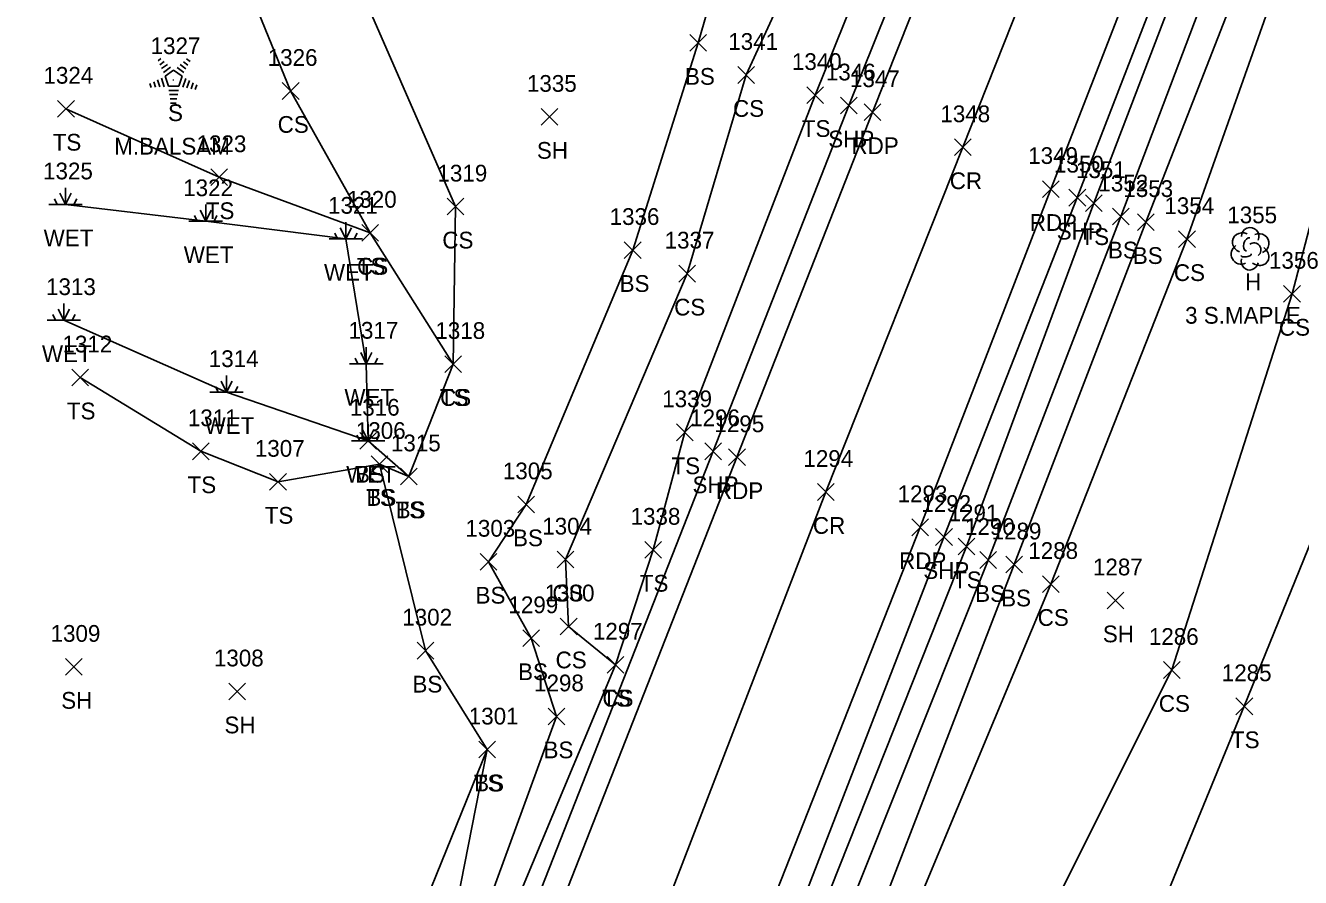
# Model space of a CAD drawing. Extents: x 1554917 to 1555870, y 813367 to 816333.
# Drawn here: x 1555040.5 to 1555192.9, y 813759.7 to 813861.5 of the extents above; entities that cross this region are included whole.
import ezdxf

# ---------------------------------------------------------------- set-up
doc = ezdxf.new("R2010")
doc.units = 0
for name, color, linetype in [('L_A', 7, 'Continuous'), ('L_C', 7, 'Continuous'), ('L_I', 7, 'Continuous'), ('L_TIC', 7, 'Continuous'), ('LELB', 7, 'Continuous'), ('LTC', 7, 'Continuous'), ('LTD', 7, 'Continuous'), ('LWET', 7, 'Continuous'), ('P_A', 7, 'Continuous'), ('P_I', 7, 'Continuous'), ('P_TIC', 7, 'Continuous'), ('PET', 7, 'Continuous'), ('PRC', 7, 'Continuous'), ('PSP', 7, 'Continuous')]:
    doc.layers.add(name, color=color, linetype=linetype)

msp = doc.modelspace()

# ---------------------------------------------------------------- linework, layer by layer
at = {"layer": 'L_TIC'}
for points in [[(1555119.88, 813858.4), (1555121.88, 813860.4)], [(1555121.88, 813858.4), (1555119.88, 813860.4)], [(1555125.62, 813854.57), (1555127.62, 813856.57)], [(1555127.62, 813854.57), (1555125.62, 813856.57)], [(1555071.21, 813852.66), (1555073.21, 813854.66)], [(1555073.21, 813852.66), (1555071.21, 813854.66)], [(1555133.87, 813852.17), (1555135.87, 813854.17)], [(1555135.87, 813852.17), (1555133.87, 813854.17)], [(1555044.37, 813850.53), (1555046.37, 813852.53)], [(1555046.37, 813850.53), (1555044.37, 813852.53)], [(1555102.14, 813849.56), (1555104.14, 813851.56)], [(1555104.14, 813849.56), (1555102.14, 813851.56)], [(1555062.66, 813842.35), (1555064.66, 813844.35)], [(1555064.66, 813842.35), (1555062.66, 813844.35)], [(1555090.89, 813838.84), (1555092.89, 813840.84)], [(1555092.89, 813838.84), (1555090.89, 813840.84)], [(1555167.16, 813839.25), (1555169.16, 813841.25)], [(1555169.16, 813839.25), (1555167.16, 813841.25)], [(1555170.4, 813837.65), (1555172.4, 813839.65)], [(1555172.4, 813837.65), (1555170.4, 813839.65)], [(1555080.71, 813835.71), (1555082.71, 813837.71)], [(1555082.71, 813835.71), (1555080.71, 813837.71)], [(1555080.71, 813835.71), (1555082.71, 813837.71)], [(1555082.71, 813835.71), (1555080.71, 813837.71)], [(1555173.38, 813836.99), (1555175.38, 813838.99)], [(1555175.38, 813836.99), (1555173.38, 813838.99)], [(1555178.29, 813834.95), (1555180.29, 813836.95)], [(1555180.29, 813834.95), (1555178.29, 813836.95)], [(1555112.07, 813833.65), (1555114.07, 813835.65)], [(1555114.07, 813833.65), (1555112.07, 813835.65)], [(1555118.58, 813830.83), (1555120.58, 813832.83)], [(1555120.58, 813830.83), (1555118.58, 813832.83)], [(1555190.84, 813828.42), (1555192.84, 813830.42)], [(1555192.84, 813828.42), (1555190.84, 813830.42)], [(1555090.62, 813820.03), (1555092.62, 813822.03)], [(1555092.62, 813820.03), (1555090.62, 813822.03)], [(1555090.62, 813820.03), (1555092.62, 813822.03)], [(1555092.62, 813820.03), (1555090.62, 813822.03)], [(1555046.07, 813818.42), (1555048.07, 813820.42)], [(1555048.07, 813818.42), (1555046.07, 813820.42)], [(1555118.3, 813811.87), (1555120.3, 813813.87)], [(1555120.3, 813811.87), (1555118.3, 813813.87)], [(1555080.46, 813810.86), (1555082.46, 813812.86)], [(1555082.46, 813810.86), (1555080.46, 813812.86)], [(1555060.49, 813809.6), (1555062.49, 813811.6)], [(1555062.49, 813809.6), (1555060.49, 813811.6)], [(1555081.82, 813808.08), (1555083.82, 813810.08)], [(1555083.82, 813808.08), (1555081.82, 813810.08)], [(1555081.82, 813808.08), (1555083.82, 813810.08)], [(1555083.82, 813808.08), (1555081.82, 813810.08)], [(1555085.32, 813806.6), (1555087.32, 813808.6)], [(1555087.32, 813806.6), (1555085.32, 813808.6)], [(1555085.32, 813806.6), (1555087.32, 813808.6)], [(1555087.32, 813806.6), (1555085.32, 813808.6)], [(1555069.7, 813805.95), (1555071.7, 813807.95)], [(1555071.7, 813805.95), (1555069.7, 813807.95)], [(1555099.34, 813803.26), (1555101.34, 813805.26)], [(1555101.34, 813803.26), (1555099.34, 813805.26)], [(1555114.51, 813797.83), (1555116.51, 813799.83)], [(1555116.51, 813797.83), (1555114.51, 813799.83)], [(1555151.94, 813798.24), (1555153.94, 813800.24)], [(1555153.94, 813798.24), (1555151.94, 813800.24)], [(1555094.86, 813796.4), (1555096.86, 813798.4)], [(1555096.86, 813796.4), (1555094.86, 813798.4)], [(1555104.04, 813796.66), (1555106.04, 813798.66)], [(1555106.04, 813796.66), (1555104.04, 813798.66)], [(1555154.55, 813796.61), (1555156.55, 813798.61)], [(1555156.55, 813796.61), (1555154.55, 813798.61)], [(1555157.65, 813796.07), (1555159.65, 813798.07)], [(1555159.65, 813796.07), (1555157.65, 813798.07)], [(1555162.02, 813793.74), (1555164.02, 813795.74)], [(1555164.02, 813793.74), (1555162.02, 813795.74)], [(1555169.75, 813791.78), (1555171.75, 813793.78)], [(1555171.75, 813791.78), (1555169.75, 813793.78)], [(1555104.42, 813788.67), (1555106.42, 813790.67)], [(1555106.42, 813788.67), (1555104.42, 813790.67)], [(1555099.94, 813787.26), (1555101.94, 813789.26)], [(1555101.94, 813787.26), (1555099.94, 813789.26)], [(1555087.32, 813785.78), (1555089.32, 813787.78)], [(1555089.32, 813785.78), (1555087.32, 813787.78)], [(1555045.31, 813783.84), (1555047.31, 813785.84)], [(1555047.31, 813783.84), (1555045.31, 813785.84)], [(1555110.01, 813784.1), (1555112.01, 813786.1)], [(1555112.01, 813784.1), (1555110.01, 813786.1)], [(1555110.01, 813784.1), (1555112.01, 813786.1)], [(1555112.01, 813784.1), (1555110.01, 813786.1)], [(1555176.49, 813783.47), (1555178.49, 813785.47)], [(1555178.49, 813783.47), (1555176.49, 813785.47)], [(1555064.82, 813780.9), (1555066.82, 813782.9)], [(1555066.82, 813780.9), (1555064.82, 813782.9)], [(1555102.98, 813777.92), (1555104.98, 813779.92)], [(1555104.98, 813777.92), (1555102.98, 813779.92)], [(1555185.14, 813779.13), (1555187.14, 813781.13)], [(1555187.14, 813779.13), (1555185.14, 813781.13)], [(1555094.69, 813773.96), (1555096.69, 813775.96)], [(1555096.69, 813773.96), (1555094.69, 813775.96)], [(1555094.69, 813773.96), (1555096.69, 813775.96)], [(1555096.69, 813773.96), (1555094.69, 813775.96)]]:
    msp.add_lwpolyline(points, dxfattribs=at)
at = {"layer": 'LELB'}
for points in [[(1555019.54, 813585.69), (1555024.77, 813597.99), (1555042.65, 813620.9), (1555048.58, 813631.85), (1555066.52, 813674.6), (1555093.66, 813750.68), (1555103.98, 813778.92), (1555100.94, 813788.26), (1555095.86, 813797.4), (1555100.34, 813804.26), (1555113.07, 813834.65), (1555120.88, 813859.4), (1555126.12, 813877.4), (1555144.96, 813909.35), (1555149.61, 813919.5), (1555153.95, 813930.09), (1555158.29, 813940)], [(1554960.86, 813387.22), (1554975.88, 813430.61), (1554997.67, 813492.71), (1555013.89, 813538.05), (1555028.68, 813579.18), (1555048.82, 813626.54), (1555068.18, 813674.18), (1555096.05, 813749.22), (1555111.01, 813785.1), (1555115.51, 813798.83), (1555119.3, 813812.87), (1555134.87, 813853.17), (1555141.95, 813870.8), (1555155.34, 813907.69), (1555153.32, 813917.67), (1555161.57, 813925.65), (1555168.92, 813938.89)], [(1555101.22, 813603.84), (1555111.95, 813631.93), (1555127.97, 813651.43), (1555152.02, 813699.54), (1555162.91, 813721.01), (1555173.86, 813750.23), (1555186.14, 813780.13), (1555202.44, 813820.35), (1555215.18, 813875.95), (1555215.28, 813897.96), (1555212.9, 813910.7), (1555212.19, 813917.21), (1555210.66, 813920.37), (1555207.16, 813922.92), (1555203.03, 813922.76), (1555199.5, 813919.6)], [(1555091.02, 813589.64), (1555093.93, 813609.08), (1555110.01, 813657.36), (1555123.68, 813699.33), (1555136.3, 813730.66), (1555163.02, 813794.74), (1555179.29, 813835.95), (1555197.25, 813886.69), (1555209.44, 813915.13), (1555210.66, 813920.37)], [(1554992.4, 813377.01), (1555009.62, 813423.34), (1555030.72, 813482.86), (1555047.7, 813528.1), (1555056, 813550.42), (1555062.05, 813566.99), (1555080.33, 813615.57), (1555099.41, 813662.25), (1555114.13, 813700.62), (1555127, 813733.84), (1555152.94, 813799.24), (1555168.16, 813840.25), (1555187.47, 813890.8), (1555199.5, 813919.6)], [(1555111.01, 813785.1), (1555105.42, 813789.67), (1555105.04, 813797.66), (1555119.58, 813831.83), (1555126.62, 813855.57), (1555135.55, 813874.97), (1555151.3, 813907.75), (1555149.61, 813919.5)], [(1554997.34, 813375.96), (1555001.03, 813380.2), (1555008.26, 813399.3), (1555016.85, 813422.36), (1555039.01, 813478.41), (1555055.21, 813525.71), (1555062.73, 813548.53), (1555066.84, 813564.4), (1555085.89, 813613.91), (1555101.8, 813661.36), (1555117.2, 813700.9), (1555129.69, 813732.82), (1555155.55, 813797.61), (1555171.4, 813838.65), (1555190.74, 813889.78), (1555201.42, 813914.42), (1555204.39, 813917.83), (1555206.44, 813916.94)], [(1555060.32, 813524.58), (1555067.83, 813537.87), (1555070.43, 813550.96), (1555072.05, 813560.86), (1555087.88, 813613.15), (1555106.35, 813658.95), (1555120.2, 813700.04), (1555133.19, 813731.1), (1555158.65, 813797.07), (1555174.38, 813837.99), (1555194.21, 813888.82), (1555206.44, 813916.94)], [(1555111.95, 813631.93), (1555123.2, 813652.42), (1555137.56, 813696.49), (1555156.74, 813743.02), (1555177.49, 813784.47), (1555191.84, 813829.42), (1555205.71, 813882.43), (1555212.9, 813910.7)], [(1555091.62, 813821.03), (1555091.89, 813839.84), (1555078.83, 813869.78), (1555066.4, 813889.61)], [(1555081.71, 813836.71), (1555072.21, 813853.66), (1555063.46, 813875.06)], [(1555086.32, 813807.6), (1555091.62, 813821.03), (1555081.71, 813836.71), (1555063.66, 813843.35), (1555045.37, 813851.53)], [(1555082.82, 813809.08), (1555070.7, 813806.95), (1555061.49, 813810.6), (1555047.07, 813819.42)], [(1554949.33, 813611.76), (1554977.21, 813618.67), (1554998.22, 813624.91), (1555016.24, 813625.01), (1555029.3, 813621.81), (1555040.32, 813624.75), (1555045.98, 813633.07), (1555049.32, 813640.6), (1555063.34, 813676.25), (1555081.89, 813724.28), (1555091.18, 813752.08), (1555095.69, 813774.96), (1555088.32, 813786.78), (1555082.82, 813809.08), (1555086.32, 813807.6), (1555081.46, 813811.86)], [(1554954.51, 813629.31), (1554971.74, 813631.07), (1554998.18, 813639.71), (1555016.83, 813638), (1555031.95, 813634.95), (1555041.94, 813634.59), (1555045.91, 813643.15), (1555048.09, 813658.42), (1555054.81, 813682.71), (1555073.55, 813727.86), (1555077.68, 813738.56), (1555087.17, 813753.94), (1555095.69, 813774.96)]]:
    msp.add_lwpolyline(points, dxfattribs=at)
at = {"layer": 'LTC'}
for p, q in [((1555056.37, 813857.26), (1555056.72, 813857.52)), ((1555059.77, 813857.5), (1555060.19, 813857.2)), ((1555056.58, 813856.8), (1555057.11, 813857.18)), ((1555056.79, 813856.33), (1555057.49, 813856.84)), ((1555057, 813855.87), (1555057.87, 813856.5)), ((1555057.22, 813855.41), (1555058.23, 813856.15)), ((1555058.23, 813856.15), (1555059.23, 813855.42)), ((1555058.65, 813856.46), (1555059.46, 813855.87)), ((1555059.02, 813856.81), (1555059.7, 813856.31)), ((1555059.39, 813857.16), (1555059.94, 813856.76)), ((1555055.4, 813854.54), (1555055.55, 813854.08)), ((1555055.86, 813854.76), (1555056.07, 813854.11)), ((1555056.31, 813854.98), (1555056.58, 813854.14)), ((1555056.77, 813855.19), (1555057.1, 813854.17)), ((1555057.22, 813855.41), (1555057.61, 813854.22)), ((1555059.23, 813855.42), (1555058.84, 813854.22)), ((1555059.67, 813855.15), (1555059.33, 813854.11)), ((1555060.11, 813854.9), (1555059.82, 813854.02)), ((1555060.56, 813854.65), (1555060.32, 813853.92)), ((1555061, 813854.4), (1555060.81, 813853.83)), ((1555058.84, 813854.22), (1555057.61, 813854.22)), ((1555058.8, 813853.72), (1555057.66, 813853.72)), ((1555058.72, 813853.22), (1555057.73, 813853.22)), ((1555058.63, 813852.72), (1555057.8, 813852.72)), ((1555058.55, 813852.22), (1555057.87, 813852.22))]:
    msp.add_line(p, q, dxfattribs=at)
at = {"layer": 'LTD'}
msp.add_line((1555186.8, 813834.85), (1555186.8, 813834.85), dxfattribs=at)
msp.add_line((1555186.8, 813834.85), (1555186.8, 813834.85), dxfattribs=at)
msp.add_arc((1555186.85, 813836.28), 1.05, 335.5272, 180.9563, dxfattribs=at)
for centre, major_axis, ratio, start_param, end_param in [((1555186.01, 813835.52), (1.21, -0.51), 0.895232, 1.570796, 4.712389), ((1555186.6, 813835.31), (-0.208, -0.792), 0.645439, 3.141593, 6.283185), ((1555187.85, 813835.43), (-1.14, -0.48), 0.949671, 1.570796, 4.712389), ((1555185.72, 813834.14), (0.58, -1.04), 0.959034, 3.141593, 6.283185), ((1555187.3, 813834.68), (-0.5, 0.667), 0.989748, 3.141593, 6.283185), ((1555187.8, 813834.02), (-1.09, 0.79), 0.841452, 1.570796, 4.712389), ((1555186.8, 813833.35), (0.26, 1.06), 0.942809, 1.570796, 4.712389), ((1555186.35, 813834.1), (-0.625, -0.083), 0.423636, 0, 3.141593)]:
    msp.add_ellipse(centre, major_axis=major_axis, ratio=ratio, start_param=start_param, end_param=end_param, dxfattribs=at)
at = {"layer": 'LWET'}
for p, q in [((1555045.32, 813840.1), (1555045.32, 813842.1)), ((1555044.32, 813840.1), (1555043.99, 813840.76)), ((1555045.32, 813840.1), (1555044.65, 813841.43)), ((1555045.32, 813840.1), (1555045.99, 813841.43)), ((1555046.32, 813840.1), (1555046.65, 813840.76)), ((1555047.32, 813840.1), (1555043.32, 813840.1)), ((1555062.06, 813838.09), (1555061.39, 813839.43)), ((1555062.06, 813838.09), (1555062.06, 813840.09)), ((1555062.06, 813838.09), (1555062.73, 813839.43)), ((1555064.06, 813838.09), (1555060.06, 813838.09)), ((1555061.06, 813838.09), (1555060.73, 813838.76)), ((1555063.06, 813838.09), (1555063.39, 813838.76)), ((1555078.81, 813835.99), (1555078.81, 813837.99)), ((1555080.81, 813835.99), (1555076.81, 813835.99)), ((1555077.81, 813835.99), (1555077.48, 813836.65)), ((1555078.81, 813835.99), (1555078.14, 813837.32)), ((1555078.81, 813835.99), (1555079.48, 813837.32)), ((1555079.81, 813835.99), (1555080.14, 813836.65)), ((1555044.12, 813826.27), (1555043.78, 813826.93)), ((1555045.12, 813826.27), (1555044.45, 813827.6)), ((1555045.12, 813826.27), (1555045.12, 813828.27)), ((1555045.12, 813826.27), (1555045.78, 813827.6)), ((1555046.12, 813826.27), (1555046.45, 813826.93)), ((1555047.12, 813826.27), (1555043.12, 813826.27)), ((1555081.25, 813821.06), (1555080.58, 813822.39)), ((1555081.25, 813821.06), (1555081.25, 813823.06)), ((1555081.25, 813821.06), (1555081.92, 813822.39)), ((1555083.25, 813821.06), (1555079.25, 813821.06)), ((1555080.25, 813821.06), (1555079.92, 813821.73)), ((1555082.25, 813821.06), (1555082.58, 813821.73)), ((1555064.55, 813817.67), (1555064.55, 813819.67)), ((1555063.55, 813817.67), (1555063.22, 813818.34)), ((1555064.55, 813817.67), (1555063.89, 813819)), ((1555064.55, 813817.67), (1555065.22, 813819)), ((1555065.55, 813817.67), (1555065.89, 813818.34)), ((1555066.55, 813817.67), (1555062.55, 813817.67)), ((1555081.46, 813811.86), (1555080.79, 813813.2)), ((1555081.46, 813811.86), (1555081.46, 813813.86)), ((1555081.46, 813811.86), (1555082.13, 813813.2)), ((1555083.46, 813811.86), (1555079.46, 813811.86)), ((1555080.46, 813811.86), (1555080.13, 813812.53)), ((1555082.46, 813811.86), (1555082.79, 813812.53))]:
    msp.add_line(p, q, dxfattribs=at)
msp.add_lwpolyline([(1555045.12, 813826.27), (1555064.55, 813817.67), (1555081.46, 813811.86), (1555081.25, 813821.06), (1555078.81, 813835.99), (1555062.06, 813838.09), (1555045.32, 813840.1)], dxfattribs=at)
at = {"layer": 'P_TIC'}
for points in [[(1555137.9, 813850.92), (1555139.9, 813852.92)], [(1555139.9, 813850.92), (1555137.9, 813852.92)], [(1555140.72, 813850.12), (1555142.72, 813852.12)], [(1555142.72, 813850.12), (1555140.72, 813852.12)], [(1555151.52, 813845.93), (1555153.52, 813847.93)], [(1555153.52, 813845.93), (1555151.52, 813847.93)], [(1555162.02, 813840.94), (1555164.02, 813842.94)], [(1555164.02, 813840.94), (1555162.02, 813842.94)], [(1555165.19, 813839.91), (1555167.19, 813841.91)], [(1555167.19, 813839.91), (1555165.19, 813841.91)], [(1555121.69, 813809.6), (1555123.69, 813811.6)], [(1555123.69, 813809.6), (1555121.69, 813811.6)], [(1555124.53, 813808.89), (1555126.53, 813810.89)], [(1555126.53, 813808.89), (1555124.53, 813810.89)], [(1555135.16, 813804.74), (1555137.16, 813806.74)], [(1555137.16, 813804.74), (1555135.16, 813806.74)], [(1555146.41, 813800.52), (1555148.41, 813802.52)], [(1555148.41, 813800.52), (1555146.41, 813802.52)], [(1555149.26, 813799.36), (1555151.26, 813801.36)], [(1555151.26, 813799.36), (1555149.26, 813801.36)]]:
    msp.add_lwpolyline(points, dxfattribs=at)
at = {"layer": 'PET'}
for points in [[(1554965.43, 813385.56), (1554980.95, 813429.92), (1555003.19, 813490.59), (1555019.55, 813535.73), (1555035.2, 813576.47), (1555053.52, 813624.76), (1555072.33, 813672.52), (1555101.11, 813747.71), (1555125.53, 813809.89), (1555141.72, 813851.12), (1555161.36, 813900.53), (1555183.5, 813956.99)], [(1554987.55, 813378.28), (1555004.34, 813425.43), (1555025.15, 813482.53), (1555042.33, 813529.78), (1555057.09, 813568.35), (1555075.57, 813617.35), (1555093.79, 813663.7), (1555108.49, 813702.81), (1555121.71, 813736.27), (1555147.41, 813801.52), (1555163.02, 813841.94), (1555182.57, 813892.25), (1555203.7, 813945.01)]]:
    msp.add_lwpolyline(points, dxfattribs=at)
at = {"layer": 'PRC'}
msp.add_lwpolyline([(1554976.76, 813382.18), (1554992.84, 813427.9), (1555014.07, 813486.01), (1555030.62, 813532.31), (1555046.37, 813573.08), (1555064.69, 813621.19), (1555082.41, 813667.53), (1555112.1, 813744.1), (1555110.69, 813739.79), (1555136.16, 813805.74), (1555152.52, 813846.93), (1555172.03, 813896.18), (1555193.96, 813951.2), (1555206.37, 813983.4), (1555218.13, 814013.22), (1555228.65, 814039.26), (1555237.93, 814064.31), (1555252.22, 814099.76), (1555265.8, 814135.89), (1555275.26, 814160.09), (1555297.17, 814214.77), (1555313.83, 814257.94), (1555329.72, 814298.26), (1555342.03, 814329.92)], dxfattribs=at)
at = {"layer": 'PSP'}
for points in [[(1554990.52, 813377.71), (1555007.26, 813424.1), (1555027.97, 813481.79), (1555045.41, 813528.93), (1555059.94, 813567), (1555096.82, 813663.08), (1555111.75, 813701.59), (1555124.82, 813734.75), (1555150.26, 813800.36), (1555166.19, 813840.91), (1555185.69, 813891.41), (1555197.67, 813922.42), (1555211.91, 813956.86)], [(1554963, 813386.3), (1554978.53, 813430.4), (1555000.44, 813491.39), (1555017.18, 813537.03), (1555032.55, 813577.93), (1555050.86, 813625.69), (1555069.49, 813673.81), (1555098.21, 813748.28), (1555122.69, 813810.6), (1555138.9, 813851.92), (1555160.79, 813906.47), (1555173.05, 813937.33)]]:
    msp.add_lwpolyline(points, dxfattribs=at)

# ---------------------------------------------------------------- texts
at = {"layer": 'L_A'}
for s, p in [('BS', (1555119.32, 813854.4)), ('S', (1555057.56, 813850.06)), ('CS', (1555125.06, 813850.57)), ('CS', (1555070.66, 813848.66)), ('TS', (1555133.28, 813848.17)), ('TS', (1555043.78, 813846.53)), ('SH', (1555101.63, 813845.56)), ('TS', (1555062.07, 813838.35)), ('WET', (1555042.7, 813835.1)), ('CS', (1555090.33, 813834.84)), ('TS', (1555166.57, 813835.25)), ('WET', (1555059.44, 813833.09)), ('BS', (1555169.85, 813833.65)), ('BS', (1555172.82, 813832.99)), ('WET', (1555076.19, 813830.99)), ('TS', (1555080.12, 813831.71)), ('CS', (1555080.15, 813831.71)), ('CS', (1555177.73, 813830.95)), ('BS', (1555111.51, 813829.65)), ('H', (1555186.24, 813829.85)), ('CS', (1555118.03, 813826.83)), ('CS', (1555190.28, 813824.42)), ('WET', (1555042.5, 813821.27)), ('WET', (1555078.63, 813816.06)), ('TS', (1555090.03, 813816.03)), ('CS', (1555090.06, 813816.03)), ('TS', (1555045.48, 813814.42)), ('WET', (1555061.93, 813812.67)), ('WET', (1555078.84, 813806.86)), ('BS', (1555079.9, 813806.86)), ('TS', (1555117.71, 813807.87)), ('TS', (1555059.9, 813805.6)), ('TS', (1555081.23, 813804.08)), ('BS', (1555081.26, 813804.08)), ('TS', (1555084.73, 813802.6)), ('BS', (1555084.76, 813802.6)), ('TS', (1555069.11, 813801.95)), ('BS', (1555098.78, 813799.26)), ('TS', (1555113.92, 813793.83)), ('TS', (1555151.35, 813794.24)), ('BS', (1555094.3, 813792.4)), ('CS', (1555103.48, 813792.66)), ('BS', (1555153.99, 813792.61)), ('BS', (1555157.09, 813792.07)), ('CS', (1555161.46, 813789.74)), ('SH', (1555169.24, 813787.78)), ('CS', (1555103.86, 813784.67)), ('BS', (1555099.38, 813783.26)), ('BS', (1555086.76, 813781.78)), ('SH', (1555044.8, 813779.84)), ('TS', (1555109.42, 813780.1)), ('CS', (1555109.45, 813780.1)), ('CS', (1555175.93, 813779.47)), ('SH', (1555064.3, 813776.9)), ('TS', (1555184.55, 813775.13)), ('BS', (1555102.42, 813773.92)), ('TS', (1555094.1, 813769.96)), ('BS', (1555094.13, 813769.96))]:
    msp.add_text(s, height=2, dxfattribs=at).set_placement(p)
at = {"layer": 'L_C'}
for s, p in [('M.BALSAM', (1555051.13, 813846.06)), ('3 S.MAPLE', (1555179.07, 813825.85))]:
    msp.add_text(s, height=2, dxfattribs=at).set_placement(p)
at = {"layer": 'L_I'}
for s, p in [('1341', (1555124.49, 813858.57)), ('1327', (1555055.48, 813858.06)), ('1326', (1555069.47, 813856.66)), ('1340', (1555132.09, 813856.17)), ('1324', (1555042.68, 813854.53)), ('1335', (1555100.44, 813853.56)), ('1323', (1555060.97, 813846.35)), ('1325', (1555042.63, 813843.1)), ('1351', (1555166.03, 813843.25)), ('1319', (1555089.75, 813842.84)), ('1352', (1555168.71, 813841.65)), ('1322', (1555059.37, 813841.09)), ('1353', (1555171.69, 813840.99)), ('1321', (1555076.68, 813838.99)), ('1320', (1555078.93, 813839.71)), ('1320', (1555078.93, 813839.71)), ('1354', (1555176.59, 813838.95)), ('1336', (1555110.32, 813837.65)), ('1355', (1555184.11, 813837.85)), ('1337', (1555116.89, 813834.83)), ('1356', (1555189.09, 813832.42)), ('1313', (1555042.99, 813829.27)), ('1317', (1555079.12, 813824.06)), ('1318', (1555089.5, 813824.03)), ('1318', (1555089.5, 813824.03)), ('1312', (1555044.95, 813822.42)), ('1314', (1555062.43, 813820.67)), ('1339', (1555116.6, 813815.87)), ('1316', (1555079.28, 813814.86)), ('1316', (1555079.28, 813814.86)), ('1311', (1555059.93, 813813.6)), ('1306', (1555080, 813812.08)), ('1306', (1555080, 813812.08)), ('1307', (1555067.93, 813809.95)), ('1315', (1555084.19, 813810.6)), ('1315', (1555084.19, 813810.6)), ('1305', (1555097.56, 813807.26)), ('1291', (1555150.81, 813802.24)), ('1304', (1555102.27, 813800.66)), ('1338', (1555112.82, 813801.83)), ('1290', (1555152.77, 813800.61)), ('1303', (1555093.09, 813800.4)), ('1289', (1555155.95, 813800.07)), ('1288', (1555160.33, 813797.74)), ('1287', (1555168.06, 813795.78)), ('1300', (1555102.56, 813792.67)), ('1302', (1555085.55, 813789.78)), ('1299', (1555098.23, 813791.26)), ('1309', (1555043.53, 813787.84)), ('1297', (1555108.32, 813788.1)), ('1297', (1555108.32, 813788.1)), ('1286', (1555174.74, 813787.47)), ('1308', (1555063.04, 813784.9)), ('1285', (1555183.45, 813783.13)), ('1298', (1555101.29, 813781.92)), ('1301', (1555093.49, 813777.96)), ('1301', (1555093.49, 813777.96))]:
    msp.add_text(s, height=2, dxfattribs=at).set_placement(p)
at = {"layer": 'LTC'}
msp.add_text('.', height=1.04, rotation=270, dxfattribs=at).set_placement((1555058.12, 813855.16))
at = {"layer": 'P_A'}
for s, p in [('SHP', (1555136.44, 813846.92)), ('RDP', (1555139.21, 813846.12)), ('CR', (1555150.95, 813841.93)), ('RDP', (1555160.51, 813836.94)), ('SHP', (1555163.73, 813835.91)), ('SHP', (1555120.22, 813805.6)), ('RDP', (1555123.02, 813804.89)), ('CR', (1555134.6, 813800.74)), ('RDP', (1555144.9, 813796.52)), ('SHP', (1555147.79, 813795.36))]:
    msp.add_text(s, height=2, dxfattribs=at).set_placement(p)
at = {"layer": 'P_I'}
for s, p in [('1346', (1555136.15, 813854.92)), ('1347', (1555139.03, 813854.12)), ('1348', (1555149.83, 813849.93)), ('1349', (1555160.32, 813844.94)), ('1350', (1555163.41, 813843.91)), ('1296', (1555119.94, 813813.6)), ('1295', (1555122.84, 813812.89)), ('1294', (1555133.47, 813808.74)), ('1293', (1555144.72, 813804.52)), ('1292', (1555147.56, 813803.36))]:
    msp.add_text(s, height=2, dxfattribs=at).set_placement(p)

doc.saveas('drawing.dxf')
